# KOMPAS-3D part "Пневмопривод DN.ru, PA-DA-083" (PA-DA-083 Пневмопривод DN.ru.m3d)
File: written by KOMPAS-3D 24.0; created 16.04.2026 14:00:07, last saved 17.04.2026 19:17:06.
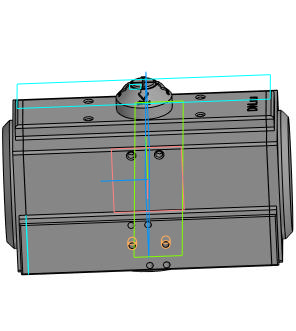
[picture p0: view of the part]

Document properties: Автор: DN.ru; Полное имя файла: C:\Работа\PA-DA-х Пневмопривод DN.ru\083\исходные материалы\PA-DA-083 Пневмопривод DN.ru.m3d

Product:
- Body: Тело 1  | qty 1
    Масса: 15.120636
- Body: Тело 2  | qty 1
    Масса: 15.120636
- Part/product: Пневмопривод DN.ru  | designation PA-DA-083
    Масса: 3.1
    Раздел спецификации: Прочие изделия
    Примечание: D290-00295

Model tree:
1. Эскиз:1
2. Элемент выдавливания:1
3. Эскиз:2  (with: Ребро.Элемент выдавливания:1)
4. Элемент выдавливания:2
5. Эскиз:3  (with: Ребро.Элемент выдавливания:2)
6. Элемент выдавливания:3  (with: Грань.Элемент выдавливания:2)
     Смещение 1 = -2; Расстояние 2 = 92.5; Смещение 2 = -2
7. Эскиз:4  (with: Грань.Элемент выдавливания:3, Ребро.Элемент выдавливания:3)
8. Элемент выдавливания:4
9. Эскиз:6  (with: Ребро.Элемент выдавливания:2)
10. Элемент выдавливания:6
11. Отверстие:2  (with: Грань.Элемент выдавливания:6)
     Глубина выреза = 10; Диаметр отверстия = 5; Угол конуса дна = 120; Расстояние 2 = 4
12. Массив по сетке:2  (with: Отверстие:2)  (3 pattern instances)
     Шаг 1 = 12; Угол раствора = 90; Шаг 2 = 32
13. Массив по сетке:3  (with: Отверстие:2)  (2 pattern instances)
     Шаг 1 = 32; Угол раствора = 90; Шаг 2 = 12
14. Отверстие:3  (with: Грань.Элемент выдавливания:6, Ребро.Элемент выдавливания:6)  (labels: W 1/4'')
     Глубина выреза = 10; Диаметр отверстия = 4.72357; Угол конуса дна = 120; Расстояние 1 = 12; Расстояние 2 = 20
15. W 1/4''  (with: Грань.Отверстие:3, Грань.Элемент выдавливания:6)  (labels: cil5_ex_DIN 477 BSW coarse)
     Длина резьбы = 8; Шаг резьбы = 1.27; Номинальный диаметр резьбы = 6.35
16. Массив по сетке:4  (with: Отверстие:3)  (labels: W 1/4'')  (2 pattern instances)
17. Эскиз:7  (with: Грань.Элемент выдавливания:2)
18. Элемент выдавливания:7
19. Эскиз:8  (with: Грань.Элемент выдавливания:2, Ребро.Элемент выдавливания:2)
20. Элемент выдавливания:8  (with: Грань.Элемент выдавливания:6)
     Расстояние 2 = 4
21. Отверстие:4  (with: Грань.Элемент выдавливания:2)
     Глубина выреза = 7; Диаметр отверстия = 5; Угол конуса дна = 118; Расстояние 1 = 6; Расстояние 2 = 10; Диаметр зенковки = 7; Глубина зенковки = 1; Угол зенковки = 90
22. Массив по сетке:5  (with: Отверстие:4)  (2 pattern instances)
     Шаг 1 = 20; Угол раствора = 90
23. Отверстие:5  (with: Грань.Элемент выдавливания:3)
     Глубина выреза = 10; Диаметр отверстия = 5; Угол конуса дна = 120; Диаметр зенковки = 7; Глубина зенковки = 1; Угол зенковки = 90
24. Массив по сетке:6  (with: Отверстие:5)  (4 pattern instances)
     Угол раствора = 90
25. Фаска:1  (with: Ребро.Элемент выдавливания:4)
     Угол = 45; Длина 1 = 10; Длина 2 = 10
26. Скругление:2  (with: Ребро.Элемент выдавливания:3)
     Радиус = 2
27. Скругление:3  (with: Ребро.Элемент выдавливания:6)
     Радиус = 2
28. Скругление:4  (with: Ребро.Элемент выдавливания:8, Ребро.Элемент выдавливания:2)
     Радиус = 2
29. Скругление:5  (with: Ребро.Элемент выдавливания:6)
     Радиус = 1
30. Смещенная плоскость:1  (with: Грань.Элемент выдавливания:3)
31. Эскиз:9
32. Элемент выдавливания:9  (with: Грань.Фаска:1)
     Расстояние 1 = 17.5642; Смещение 1 = 1
33. Смещенная плоскость:2  (with: Грань.Элемент выдавливания:4)
     Расстояние = 0.5
34. Эскиз:10
35. Элемент выдавливания:10
     Расстояние 1 = 10.9142
36. Эскиз:11  (with: Грань.Элемент выдавливания:4)
37. Элемент выдавливания:11
     Расстояние 1 = 1
38. Эскиз:12  (with: Грань.Элемент выдавливания:11)
39. Элемент выдавливания:12  (with: Грань.Элемент выдавливания:4)
     Расстояние 2 = 1
40. Эскиз:13  (with: Грань.Элемент выдавливания:11)
41. Элемент выдавливания:13  (with: Грань.Элемент выдавливания:4)
     Расстояние 2 = 1
42. Скругление:7  (with: Ребро.Элемент выдавливания:11)
     Радиус = 1
43. Скругление:8  (with: Ребро.Элемент выдавливания:8)
     Радиус = 2
44. Эскиз:14  (with: Грань.Элемент выдавливания:3)
45. Элемент выдавливания:14  (with: Грань.Фаска:1)
     Расстояние 1 = 29.1414; Смещение 1 = 0.1
46. Эскиз:15  (with: Грань.Элемент выдавливания:3, Ребро.Скругление:2)
47. Элемент выдавливания:15
     Расстояние 2 = 0.1
48. Отверстие:6  (with: Грань.Элемент выдавливания:2, Ребро.Элемент выдавливания:2)
     Глубина выреза = 10; Диаметр отверстия = 8; Угол конуса дна = 118; Расстояние 1 = 8; Расстояние 2 = 8
49. Зеркальный массив:1
50. Экземпляр ( 1 )
51. Экземпляр ( 2 )  (with: Отверстие:6)
52. Зеркальный массив:2  (with: Экземпляр ( 1 ), Экземпляр ( 2 ), Отверстие:6)
53. Зеркальный массив:3  (with: Экземпляр ( 1 ), Экземпляр ( 2 ), Зеркальный массив:2, Отверстие:6)
54. Зеркальный массив:4  (with: Экземпляр ( 1 ), Экземпляр ( 2 ), Зеркальный массив:1, Отверстие:6, Зеркальный массив:3, Зеркальный массив:2)
55. Фаска:2  (with: Ребро.Элемент выдавливания:7)
     Угол = 45; Длина 1 = 1; Длина 2 = 1
56. Фаска:3  (with: Ребро.Элемент выдавливания:1)
     Угол = 45; Длина 1 = 5; Длина 2 = 5
57. Смещенная плоскость:3  (with: Грань.Элемент выдавливания:6)
     Расстояние = 5
58. Эскиз:16
59. Элемент выдавливания:16
     Расстояние 2 = 0.1
60. Зеркальный массив:5  (with: Экземпляр ( 1 ), Экземпляр ( 2 ), Элемент выдавливания:16)

Expressions: H/2; -G/2; (E-C-4.5)/2
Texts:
  PA-DA-083
  GOST 26.020 Pr3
